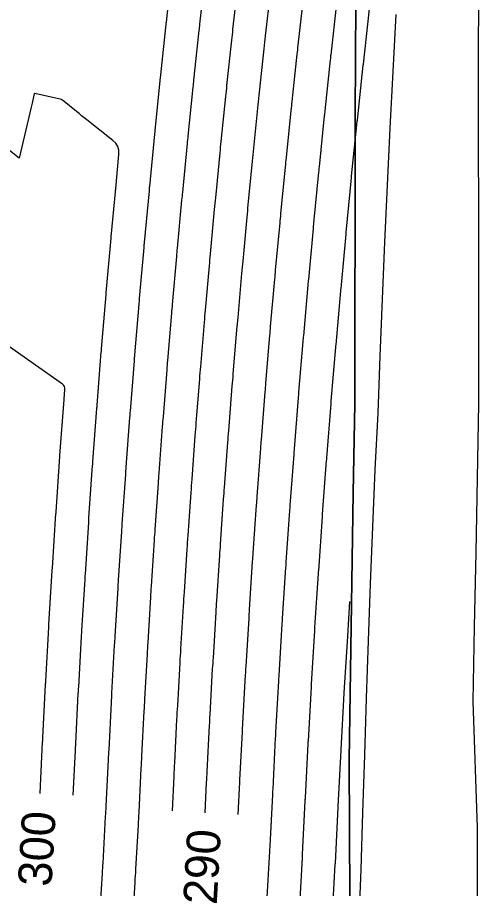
# Model space of a CAD drawing. Extents: x 1710723 to 1713003, y 548603 to 551142.
# Drawn here: x 1712408.5 to 1712491.9, y 550142.9 to 550298.2 of the extents above; entities that cross this region are included whole.
import ezdxf

# ---------------------------------------------------------------- set-up
doc = ezdxf.new("R2010")
doc.units = 0
for name, color, linetype in [('R_Contour Annot', 7, 'Continuous'), ('R_Contours', 7, 'Continuous'), ('R_MOT', 7, 'Continuous'), ('R_No Plot', 7, 'Continuous')]:
    doc.layers.add(name, color=color, linetype=linetype)

msp = doc.modelspace()

# ---------------------------------------------------------------- linework, layer by layer
at = {"layer": 'R_Contours'}
for points in [[(1712436.14, 550307.6), (1712435.06, 550297.92), (1712435.05, 550297.82), (1712435.04, 550297.73), (1712435.03, 550297.63), (1712435.02, 550297.53), (1712434, 550287.97), (1712433.99, 550287.84), (1712433.97, 550287.71), (1712433.96, 550287.58), (1712433.95, 550287.46), (1712432.98, 550278.01), (1712432.97, 550277.85), (1712432.95, 550277.69), (1712432.93, 550277.53), (1712432.92, 550277.37), (1712432.01, 550268.04), (1712431.99, 550267.85), (1712431.97, 550267.66), (1712431.96, 550267.47), (1712431.94, 550267.28), (1712431.08, 550258.05), (1712431.06, 550257.83), (1712431.04, 550257.62), (1712431.02, 550257.4), (1712431, 550257.18), (1712430.2, 550248.05), (1712430.18, 550247.81), (1712430.16, 550247.56), (1712430.14, 550247.32), (1712430.12, 550247.08), (1712429.36, 550238.04), (1712429.34, 550237.77), (1712429.32, 550237.5), (1712429.29, 550237.23), (1712429.27, 550236.96), (1712428.57, 550228.01), (1712428.54, 550227.72), (1712428.52, 550227.43), (1712428.5, 550227.13), (1712428.48, 550226.84), (1712427.82, 550217.98), (1712427.79, 550217.66), (1712427.77, 550217.34), (1712427.75, 550217.02), (1712427.73, 550216.71), (1712427.11, 550207.93), (1712427.09, 550207.59), (1712427.07, 550207.25), (1712427.04, 550206.9), (1712427.02, 550206.56), (1712426.45, 550197.87), (1712426.43, 550197.51), (1712426.41, 550197.14), (1712426.38, 550196.78), (1712426.36, 550196.41), (1712425.84, 550187.8), (1712425.82, 550187.41), (1712425.79, 550187.03), (1712425.77, 550186.64), (1712425.75, 550186.25), (1712425.27, 550177.72), (1712425.25, 550177.31), (1712425.23, 550176.9), (1712425.2, 550176.49), (1712425.18, 550176.08), (1712424.75, 550167.62), (1712424.73, 550167.19), (1712424.7, 550166.76), (1712424.68, 550166.33), (1712424.66, 550165.91), (1712424.24, 550157.52), (1712424.22, 550157.07), (1712424.19, 550156.63), (1712424.17, 550156.18), (1712424.14, 550155.73), (1712423.68, 550147.43), (1712423.65, 550146.97), (1712423.62, 550146.5), (1712423.59, 550146.03), (1712423.57, 550145.57), (1712423.05, 550137.35)], [(1712441.95, 550305.87), (1712440.96, 550296.97), (1712440.92, 550296.68), (1712440.89, 550296.4), (1712440.86, 550296.11), (1712440.83, 550295.82), (1712439.89, 550287), (1712439.86, 550286.7), (1712439.83, 550286.39), (1712439.79, 550286.08), (1712439.76, 550285.77), (1712438.87, 550277.03), (1712438.84, 550276.7), (1712438.8, 550276.36), (1712438.77, 550276.03), (1712438.74, 550275.7), (1712437.89, 550267.04), (1712437.86, 550266.68), (1712437.83, 550266.33), (1712437.79, 550265.98), (1712437.76, 550265.62), (1712436.96, 550257.04), (1712436.93, 550256.66), (1712436.89, 550256.29), (1712436.86, 550255.91), (1712436.83, 550255.54), (1712436.08, 550247.03), (1712436.04, 550246.63), (1712436.01, 550246.23), (1712435.97, 550245.84), (1712435.94, 550245.44), (1712435.24, 550237), (1712435.2, 550236.59), (1712435.17, 550236.17), (1712435.13, 550235.75), (1712435.1, 550235.34), (1712434.44, 550226.97), (1712434.41, 550226.53), (1712434.37, 550226.1), (1712434.34, 550225.66), (1712434.31, 550225.23), (1712433.69, 550216.92), (1712433.66, 550216.47), (1712433.62, 550216.01), (1712433.59, 550215.56), (1712433.56, 550215.1), (1712432.98, 550206.87), (1712432.95, 550206.39), (1712432.92, 550205.92), (1712432.89, 550205.44), (1712432.86, 550204.97), (1712432.32, 550196.8), (1712432.29, 550196.31), (1712432.26, 550195.81), (1712432.23, 550195.32), (1712432.2, 550194.83), (1712431.71, 550186.72), (1712431.68, 550186.21), (1712431.65, 550185.7), (1712431.62, 550185.19), (1712431.59, 550184.67), (1712431.14, 550176.63), (1712431.11, 550176.1), (1712431.08, 550175.57), (1712431.05, 550175.04), (1712431.02, 550174.51), (1712430.61, 550166.53), (1712430.58, 550165.98), (1712430.55, 550165.44), (1712430.53, 550164.89), (1712430.5, 550164.34), (1712430.1, 550156.42), (1712430.07, 550155.86), (1712430.04, 550155.3), (1712430.01, 550154.73), (1712429.98, 550154.17), (1712429.54, 550146.32), (1712429.51, 550145.75), (1712429.47, 550145.17), (1712429.44, 550144.6), (1712429.4, 550144.02), (1712428.91, 550136.24)], [(1712447.75, 550304.15), (1712446.85, 550296.02), (1712446.8, 550295.54), (1712446.74, 550295.07), (1712446.69, 550294.59), (1712446.64, 550294.12), (1712445.78, 550286.04), (1712445.73, 550285.55), (1712445.68, 550285.06), (1712445.63, 550284.57), (1712445.58, 550284.08), (1712444.76, 550276.05), (1712444.71, 550275.54), (1712444.65, 550275.03), (1712444.6, 550274.53), (1712444.56, 550274.02), (1712443.78, 550266.04), (1712443.73, 550265.52), (1712443.68, 550265), (1712443.63, 550264.48), (1712443.58, 550263.96), (1712442.84, 550256.03), (1712442.79, 550255.49), (1712442.75, 550254.96), (1712442.7, 550254.42), (1712442.65, 550253.89), (1712441.96, 550246), (1712441.91, 550245.45), (1712441.86, 550244.91), (1712441.81, 550244.36), (1712441.77, 550243.81), (1712441.11, 550235.97), (1712441.07, 550235.41), (1712441.02, 550234.84), (1712440.97, 550234.28), (1712440.93, 550233.71), (1712440.31, 550225.92), (1712440.27, 550225.35), (1712440.22, 550224.77), (1712440.18, 550224.19), (1712440.14, 550223.61), (1712439.56, 550215.87), (1712439.52, 550215.28), (1712439.47, 550214.68), (1712439.43, 550214.09), (1712439.39, 550213.5), (1712438.85, 550205.8), (1712438.81, 550205.2), (1712438.77, 550204.59), (1712438.73, 550203.98), (1712438.69, 550203.37), (1712438.19, 550195.73), (1712438.15, 550195.11), (1712438.11, 550194.48), (1712438.07, 550193.86), (1712438.03, 550193.24), (1712437.57, 550185.6), (1712437.53, 550184.98), (1712437.5, 550184.37), (1712437.46, 550183.75), (1712437.43, 550183.14), (1712437, 550175.45), (1712436.96, 550174.85), (1712436.93, 550174.24), (1712436.9, 550173.64), (1712436.87, 550173.04), (1712436.47, 550165.29), (1712436.44, 550164.7), (1712436.41, 550164.11), (1712436.38, 550163.52), (1712436.35, 550162.92), (1712436.04, 550156.74)], [(1712441.94, 550156.4), (1712442.21, 550161.82), (1712442.23, 550162.3), (1712442.26, 550162.78), (1712442.28, 550163.26), (1712442.31, 550163.73), (1712442.73, 550171.94), (1712442.76, 550172.43), (1712442.78, 550172.91), (1712442.81, 550173.4), (1712442.83, 550173.89), (1712443.29, 550182.05), (1712443.32, 550182.54), (1712443.35, 550183.04), (1712443.38, 550183.53), (1712443.41, 550184.03), (1712443.9, 550192.15), (1712443.93, 550192.65), (1712443.96, 550193.15), (1712443.99, 550193.66), (1712444.03, 550194.16), (1712444.55, 550202.24), (1712444.59, 550202.75), (1712444.62, 550203.26), (1712444.66, 550203.77), (1712444.69, 550204.28), (1712445.25, 550212.31), (1712445.29, 550212.83), (1712445.33, 550213.35), (1712445.36, 550213.88), (1712445.4, 550214.4), (1712446, 550222.38), (1712446.04, 550222.91), (1712446.08, 550223.44), (1712446.12, 550223.97), (1712446.16, 550224.5), (1712446.78, 550232.43), (1712446.83, 550232.97), (1712446.87, 550233.51), (1712446.92, 550234.05), (1712446.96, 550234.59), (1712447.62, 550242.48), (1712447.67, 550243.03), (1712447.71, 550243.58), (1712447.76, 550244.12), (1712447.81, 550244.67), (1712448.5, 550252.52), (1712448.55, 550253.08), (1712448.6, 550253.63), (1712448.65, 550254.18), (1712448.7, 550254.74), (1712449.42, 550262.55), (1712449.48, 550263.11), (1712449.53, 550263.67), (1712449.58, 550264.23), (1712449.64, 550264.79), (1712450.39, 550272.57), (1712450.45, 550273.14), (1712450.51, 550273.71), (1712450.56, 550274.27), (1712450.62, 550274.84), (1712451.41, 550282.58), (1712451.47, 550283.15), (1712451.53, 550283.73), (1712451.59, 550284.3), (1712451.65, 550284.88), (1712452.47, 550292.58), (1712452.53, 550293.16), (1712452.6, 550293.74), (1712452.66, 550294.32), (1712452.72, 550294.9), (1712453.58, 550302.57)], [(1712447.84, 550156.07), (1712448.07, 550160.72), (1712448.09, 550161.08), (1712448.11, 550161.45), (1712448.13, 550161.81), (1712448.15, 550162.18), (1712448.59, 550170.85), (1712448.61, 550171.22), (1712448.63, 550171.59), (1712448.65, 550171.96), (1712448.67, 550172.32), (1712449.16, 550180.96), (1712449.18, 550181.34), (1712449.2, 550181.71), (1712449.22, 550182.09), (1712449.25, 550182.46), (1712449.77, 550191.07), (1712449.79, 550191.45), (1712449.81, 550191.83), (1712449.84, 550192.21), (1712449.86, 550192.58), (1712450.42, 550201.16), (1712450.45, 550201.55), (1712450.47, 550201.93), (1712450.5, 550202.31), (1712450.53, 550202.7), (1712451.12, 550211.25), (1712451.15, 550211.64), (1712451.18, 550212.03), (1712451.21, 550212.41), (1712451.23, 550212.8), (1712451.87, 550221.33), (1712451.9, 550221.72), (1712451.93, 550222.11), (1712451.96, 550222.5), (1712451.99, 550222.89), (1712452.66, 550231.39), (1712452.69, 550231.79), (1712452.72, 550232.18), (1712452.75, 550232.58), (1712452.79, 550232.98), (1712453.5, 550241.45), (1712453.53, 550241.85), (1712453.56, 550242.25), (1712453.6, 550242.65), (1712453.63, 550243.05), (1712454.38, 550251.5), (1712454.41, 550251.9), (1712454.45, 550252.3), (1712454.49, 550252.7), (1712454.52, 550253.1), (1712455.31, 550261.54), (1712455.34, 550261.94), (1712455.38, 550262.34), (1712455.42, 550262.75), (1712455.46, 550263.15), (1712456.28, 550271.57), (1712456.32, 550271.98), (1712456.36, 550272.38), (1712456.4, 550272.78), (1712456.44, 550273.18), (1712457.3, 550281.6), (1712457.34, 550282), (1712457.38, 550282.4), (1712457.42, 550282.8), (1712457.46, 550283.2), (1712458.36, 550291.61), (1712458.4, 550292.01), (1712458.45, 550292.41), (1712458.49, 550292.81), (1712458.54, 550293.21), (1712459.47, 550301.62)], [(1712465.37, 550300.66), (1712464.35, 550291.52), (1712464.32, 550291.3), (1712464.3, 550291.08), (1712464.28, 550290.86), (1712464.25, 550290.64), (1712463.28, 550281.53), (1712463.26, 550281.3), (1712463.23, 550281.07), (1712463.21, 550280.84), (1712463.18, 550280.61), (1712462.26, 550271.52), (1712462.23, 550271.28), (1712462.21, 550271.05), (1712462.19, 550270.81), (1712462.16, 550270.58), (1712461.28, 550261.5), (1712461.26, 550261.26), (1712461.23, 550261.02), (1712461.21, 550260.77), (1712461.19, 550260.53), (1712460.35, 550251.47), (1712460.32, 550251.22), (1712460.3, 550250.97), (1712460.28, 550250.73), (1712460.26, 550250.48), (1712459.46, 550241.42), (1712459.44, 550241.17), (1712459.41, 550240.92), (1712459.39, 550240.67), (1712459.37, 550240.42), (1712458.62, 550231.36), (1712458.59, 550231.11), (1712458.57, 550230.86), (1712458.55, 550230.6), (1712458.53, 550230.35), (1712457.82, 550221.29), (1712457.8, 550221.04), (1712457.78, 550220.78), (1712457.76, 550220.53), (1712457.74, 550220.27), (1712457.07, 550211.21), (1712457.05, 550210.95), (1712457.03, 550210.7), (1712457.01, 550210.44), (1712456.99, 550210.19), (1712456.36, 550201.11), (1712456.34, 550200.86), (1712456.32, 550200.6), (1712456.31, 550200.35), (1712456.29, 550200.09), (1712455.7, 550191.01), (1712455.68, 550190.75), (1712455.67, 550190.5), (1712455.65, 550190.24), (1712455.63, 550189.99), (1712455.08, 550180.89), (1712455.07, 550180.64), (1712455.05, 550180.38), (1712455.04, 550180.13), (1712455.02, 550179.87), (1712454.51, 550170.76), (1712454.5, 550170.51), (1712454.48, 550170.26), (1712454.47, 550170), (1712454.46, 550169.75), (1712453.99, 550160.62), (1712453.97, 550160.37), (1712453.96, 550160.12), (1712453.95, 550159.87), (1712453.94, 550159.62), (1712453.48, 550150.48), (1712453.47, 550150.23), (1712453.45, 550149.98), (1712453.44, 550149.73), (1712453.42, 550149.48), (1712452.91, 550140.36)], [(1712458.75, 550138.81), (1712459.29, 550148.37), (1712459.3, 550148.51), (1712459.3, 550148.65), (1712459.31, 550148.79), (1712459.32, 550148.93), (1712459.8, 550158.51), (1712459.81, 550158.65), (1712459.81, 550158.79), (1712459.82, 550158.93), (1712459.83, 550159.07), (1712460.32, 550168.66), (1712460.33, 550168.79), (1712460.34, 550168.93), (1712460.34, 550169.06), (1712460.35, 550169.2), (1712460.89, 550178.79), (1712460.9, 550178.92), (1712460.9, 550179.05), (1712460.91, 550179.19), (1712460.92, 550179.32), (1712461.5, 550188.91), (1712461.51, 550189.04), (1712461.52, 550189.17), (1712461.53, 550189.3), (1712461.53, 550189.43), (1712462.16, 550199.02), (1712462.17, 550199.15), (1712462.18, 550199.27), (1712462.18, 550199.4), (1712462.19, 550199.52), (1712462.86, 550209.13), (1712462.87, 550209.25), (1712462.88, 550209.37), (1712462.89, 550209.49), (1712462.9, 550209.61), (1712463.61, 550219.22), (1712463.62, 550219.34), (1712463.63, 550219.45), (1712463.64, 550219.57), (1712463.65, 550219.69), (1712464.41, 550229.3), (1712464.42, 550229.41), (1712464.43, 550229.53), (1712464.43, 550229.64), (1712464.44, 550229.75), (1712465.25, 550239.38), (1712465.26, 550239.49), (1712465.27, 550239.59), (1712465.27, 550239.69), (1712465.28, 550239.8), (1712466.14, 550249.46), (1712466.14, 550249.55), (1712466.15, 550249.64), (1712466.16, 550249.74), (1712466.17, 550249.83), (1712467.07, 550259.52), (1712467.08, 550259.6), (1712467.08, 550259.69), (1712467.09, 550259.77), (1712467.1, 550259.85), (1712468.05, 550269.58), (1712468.05, 550269.65), (1712468.06, 550269.72), (1712468.07, 550269.79), (1712468.07, 550269.86), (1712469.07, 550279.63), (1712469.08, 550279.69), (1712469.08, 550279.74), (1712469.09, 550279.8), (1712469.09, 550279.85), (1712470.14, 550289.67), (1712470.15, 550289.71), (1712470.15, 550289.75), (1712470.16, 550289.79), (1712470.16, 550289.84), (1712471.26, 550299.71)], [(1712418.42, 550159.51), (1712418.82, 550167.47), (1712418.84, 550167.78), (1712418.85, 550168.09), (1712418.87, 550168.41), (1712418.88, 550168.72), (1712419.34, 550177.65), (1712419.36, 550177.94), (1712419.37, 550178.23), (1712419.39, 550178.52), (1712419.41, 550178.8), (1712419.91, 550187.83), (1712419.93, 550188.09), (1712419.94, 550188.35), (1712419.96, 550188.62), (1712419.97, 550188.88), (1712420.53, 550198), (1712420.54, 550198.23), (1712420.56, 550198.47), (1712420.57, 550198.71), (1712420.59, 550198.94), (1712421.19, 550208.16), (1712421.2, 550208.37), (1712421.21, 550208.57), (1712421.23, 550208.78), (1712421.24, 550208.99), (1712421.89, 550218.31), (1712421.91, 550218.49), (1712421.92, 550218.67), (1712421.93, 550218.85), (1712421.95, 550219.03), (1712422.65, 550228.45), (1712422.66, 550228.6), (1712422.67, 550228.75), (1712422.68, 550228.9), (1712422.69, 550229.05), (1712423.44, 550238.59), (1712423.45, 550238.71), (1712423.46, 550238.83), (1712423.47, 550238.95), (1712423.48, 550239.07), (1712424.29, 550248.71), (1712424.3, 550248.8), (1712424.3, 550248.89), (1712424.31, 550248.98), (1712424.32, 550249.07), (1712425.18, 550258.83), (1712425.19, 550258.89), (1712425.19, 550258.94), (1712425.2, 550259), (1712425.2, 550259.06), (1712426.12, 550268.94), (1712426.12, 550268.99), (1712426.13, 550269.03), (1712426.59, 550273.77), (1712426.58, 550274.5), (1712426.4, 550275.16), (1712426.04, 550275.75), (1712425.52, 550276.26), (1712420.84, 550279.93), (1712420.38, 550280.29), (1712419.93, 550280.65), (1712419.47, 550281.02), (1712419.02, 550281.38), (1712416.49, 550283.43), (1712416.39, 550283.49), (1712416.3, 550283.55), (1712416.19, 550283.59), (1712416.08, 550283.62), (1712411.59, 550284.64), (1712411.56, 550284.64), (1712411.53, 550284.64), (1712411.51, 550284.61), (1712411.49, 550284.58), (1712411.16, 550283.16), (1712411.1, 550282.92), (1712411.05, 550282.67), (1712410.99, 550282.42), (1712410.93, 550282.17), (1712408.8, 550273.08), (1712408.8, 550273.08), (1712408.8, 550273.08), (1712408.8, 550273.08), (1712408.79, 550273.08), (1712397.07, 550282.27)], [(1712412.52, 550159.86), (1712412.98, 550169.03), (1712412.99, 550169.23), (1712413, 550169.42), (1712413.01, 550169.62), (1712413.02, 550169.81), (1712413.5, 550179.22), (1712413.51, 550179.39), (1712413.52, 550179.56), (1712413.53, 550179.73), (1712413.54, 550179.89), (1712414.07, 550189.41), (1712414.08, 550189.55), (1712414.09, 550189.68), (1712414.1, 550189.82), (1712414.11, 550189.96), (1712414.69, 550199.58), (1712414.7, 550199.69), (1712414.7, 550199.8), (1712414.71, 550199.91), (1712414.72, 550200.01), (1712415.35, 550209.75), (1712415.36, 550209.83), (1712415.36, 550209.9), (1712415.37, 550209.98), (1712415.37, 550210.05), (1712416.06, 550219.91), (1712416.06, 550219.96), (1712416.07, 550220), (1712416.07, 550220.04), (1712416.07, 550220.08), (1712416.82, 550230.07), (1712416.82, 550230.1), (1712416.96, 550231.86), (1712416.95, 550232.14), (1712416.87, 550232.38), (1712416.74, 550232.59), (1712416.53, 550232.77), (1712407.07, 550239.45)], [(1712464.59, 550137.27), (1712465.15, 550147.26), (1712465.15, 550147.29), (1712465.16, 550147.32), (1712465.16, 550147.35), (1712465.16, 550147.39), (1712465.66, 550157.41), (1712465.67, 550157.49), (1712465.67, 550157.51), (1712466.18, 550167.56), (1712466.19, 550167.6), (1712466.19, 550167.64), (1712466.75, 550177.7), (1712466.76, 550177.74), (1712466.76, 550177.75), (1712467.37, 550187.83), (1712467.37, 550187.85), (1712467.77, 550194.08)]]:
    msp.add_lwpolyline(points, dxfattribs=at)
at = {"layer": 'R_MOT'}
for points in [[(1712467.79, 550127.25), (1712467.73, 550141.12), (1712467.61, 550165.79), (1712467.86, 550181.67), (1712468.11, 550197.55), (1712468.36, 550213.43), (1712468.61, 550229.32), (1712468.64, 550245.44), (1712468.67, 550261.56), (1712468.7, 550277.69), (1712468.73, 550293.81), (1712468.98, 550310.3), (1712469.24, 550326.8), (1712469.49, 550343.3), (1712469.75, 550359.79), (1712469.93, 550375.99), (1712470.11, 550392.19), (1712470.12, 550392.31)], [(1712490.97, 550013.23), (1712491.94, 550015.81), (1712490.81, 550030.23), (1712490.18, 550045.8), (1712489.54, 550061.38), (1712489.79, 550075.28), (1712490.03, 550089.19), (1712490.27, 550103.09), (1712490.52, 550117), (1712490.5, 550135.38), (1712490.48, 550153.76), (1712489.73, 550176.25), (1712489.99, 550189.52), (1712490.24, 550202.78), (1712490.5, 550216.05), (1712490.75, 550229.31), (1712490.74, 550245.46), (1712490.72, 550261.61), (1712490.7, 550277.75), (1712490.68, 550293.9), (1712490.89, 550310.22)], [(1712475.95, 550298.69), (1712475.41, 550288.56), (1712474.87, 550278.43), (1712474.38, 550268.28), (1712473.91, 550258.13), (1712473.48, 550247.98), (1712473.08, 550237.81), (1712472.72, 550227.64), (1712472.23, 550217.5), (1712471.78, 550207.34), (1712471.35, 550197.19), (1712470.99, 550187.02), (1712470.66, 550176.84), (1712470.35, 550166.65), (1712470.03, 550156.47), (1712469.68, 550146.29), (1712469.33, 550137.29)], [(1712475.95, 550298.69), (1712475.41, 550288.56), (1712474.87, 550278.43), (1712474.38, 550268.28), (1712473.91, 550258.13), (1712473.48, 550247.98), (1712473.08, 550237.81), (1712472.72, 550227.64), (1712472.23, 550217.5), (1712471.78, 550207.34), (1712471.35, 550197.19), (1712470.99, 550187.02), (1712470.66, 550176.84), (1712470.35, 550166.65), (1712470.03, 550156.47), (1712469.68, 550146.29), (1712469.33, 550137.29)]]:
    msp.add_lwpolyline(points, dxfattribs=at)
at = {"layer": 'R_No Plot'}
msp.add_lwpolyline([(1712468.98, 550310.3), (1712468.73, 550293.81), (1712468.7, 550277.69), (1712468.67, 550261.56), (1712468.64, 550245.44), (1712468.61, 550229.32), (1712468.36, 550213.43), (1712468.11, 550197.55), (1712467.86, 550181.67), (1712467.61, 550165.79), (1712467.73, 550141.12), (1712467.84, 550116.46), (1712467.53, 550095.6), (1712466.2, 550089.23), (1712466.46, 550075.55), (1712466.71, 550061.86), (1712467.06, 550048.77), (1712467.41, 550035.68), (1712467.77, 550022.58), (1712468.12, 550009.49), (1712463.76, 550001.4), (1712464.35, 549999.67)], dxfattribs=at)

# ---------------------------------------------------------------- texts
at = {"layer": 'R_Contour Annot'}
for s, rotation, p in [('300', 86.6339, (1712414.54, 550143.13)), ('290', 86.7643, (1712444.01, 550139.91))]:
    msp.add_text(s, height=6, rotation=rotation, dxfattribs=at).set_placement(p)

doc.saveas('drawing.dxf')
